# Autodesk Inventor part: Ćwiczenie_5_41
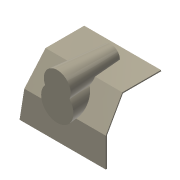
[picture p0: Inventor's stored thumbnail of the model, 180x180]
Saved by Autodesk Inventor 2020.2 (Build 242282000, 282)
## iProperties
Created: 2005-04
Part Number: Ćwiczenie_5_41
Document SubType Name: Modeling
Designer: F.Stasiak
Manufacturer: Standard
Standards Organization: Custom
Density: 1 g/cm^3
Material: Ogólny
Appearance: Jasnobeżowa
Manager: www.cadconsulting.pl
Company: Fabian Stasiak CAD Consulting
Author: F.Stasiak
Subject: Zbiór ćwiczeń. Autodesk Inventor 2020. Kurs podstawowy
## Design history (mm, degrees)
sketch "Szkic1"
  geometry: L1 (-40, -30)-(40, -30); L2 (40, -30)-(40, 30); L3 (40, 30)-(-40, 30); L4 (-40, 30)-(-40, -30); L5 (0, 30)-(0, -30); 2 further points
  constraints: 10 end point, 3 midpoint, 2 parallel, 1 coincident, 1 horizontal, 1 perpendicular
  dimensions: "d0" = 80 distance of L1.start L1.end; "d1" = 60 distance of L3.end L1.start
extrude "Wyciągnięcie proste1" new body sketch "Szkic1" distance "d2" = 50; taper "d3" = -5 deg
sketch "Szkic2"
  geometry: L1 (0, 0)-(4.374, 50.191) reference; L2 (80, 0)-(75.626, 50.191) reference; L3 (2.187, 25.095)-(77.813, 25.095)
  constraints: 2 end point, 2 midpoint
feature "Podział1" sketch "Szkic2"
feature "Szkic powierzchni1" dims angle "d4" = 30 deg
node "Płaszczyzna konstrukcyjna1"
sketch "Szkic3"
  geometry: L1 (-35.626, 50)-(35.626, 50) reference; L2 (0, 50)-(0, 35); L3 (40, 0)-(-40, 0) reference; A1 r 12.5 centre (0, 50) between (11.363, 44.792) and (-11.363, 44.792); A2 r 15 centre (0, 35) between (-11.363, 44.792) and (11.363, 44.792); 2 further points
  constraints: 4 point on circle, 2 centre point, 2 end point, 1 midpoint, 1 point on line, 1 vertical
  dimensions: "d18" = 25 diameter of A1; "d19" = 30 diameter of A2; "d20" = 0 distance from line of L1 L2.start; "d21" = 15 distance of L2.start L2.end
extrude "Wyciągnięcie proste2" join sketch "Szkic3" distance "d9" = 50; taper "d10" = -5 deg
feature "Skorupa1" dims "d11" = 1
node "Bryła1"
node "Korpusy bryłowe"
node "Korpusy powierzchniowe"
other parameters: "d5" = -35
